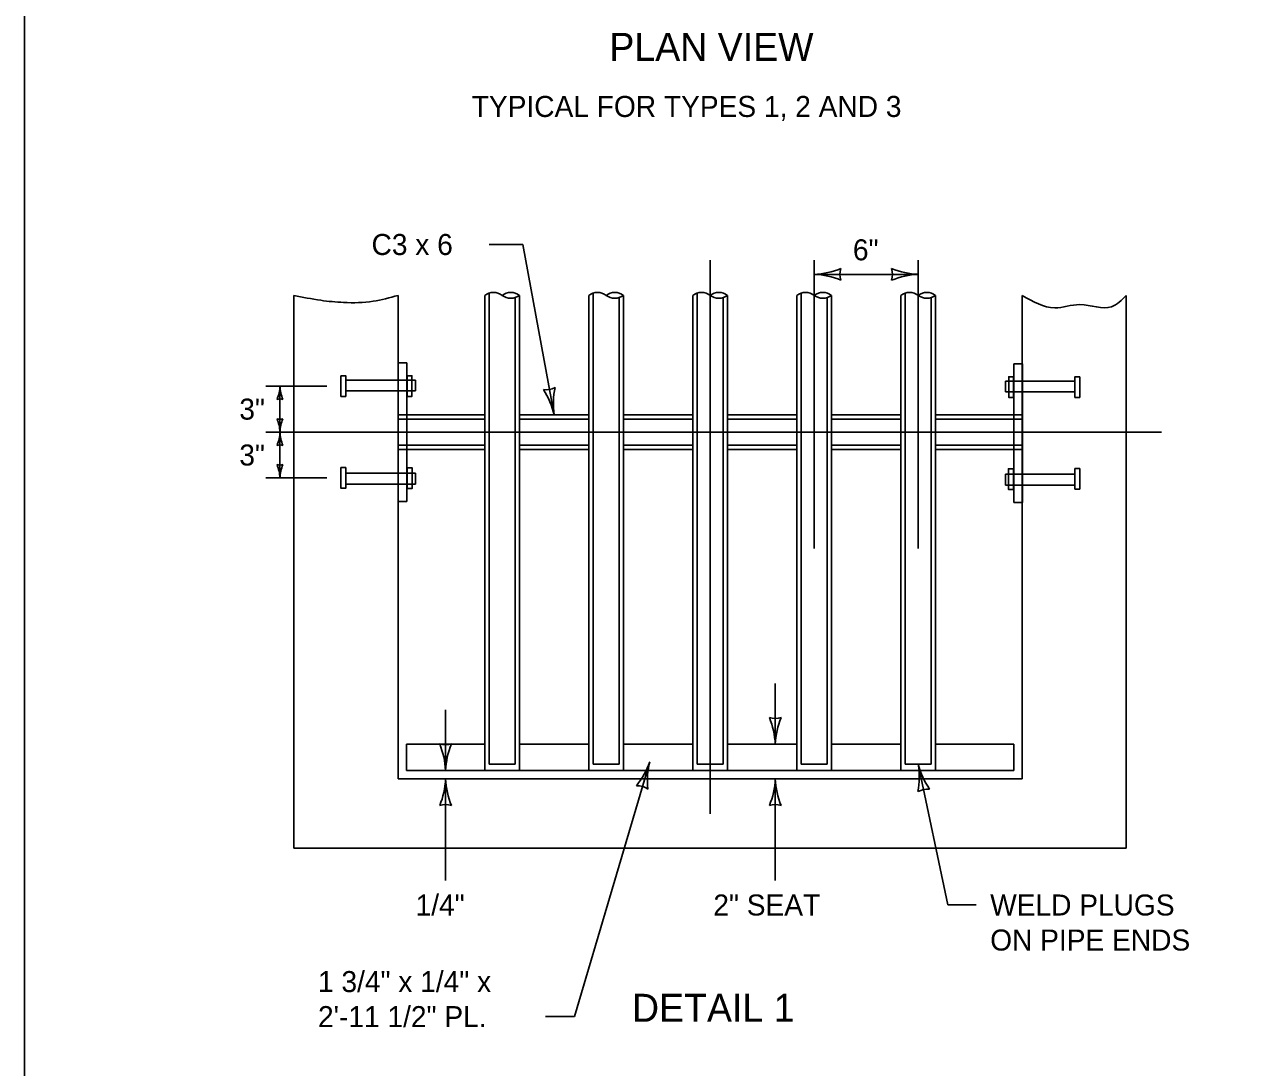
# Model space of a CAD drawing. Extents: x 49991.4 to 50021, y 49987.6 to 50011.4.
# Drawn here: x 49999.384 to 50002.895, y 49992.708 to 49995.684 of the extents above; entities that cross this region are included whole.
import ezdxf

# ---------------------------------------------------------------- set-up
doc = ezdxf.new("R2010")
doc.units = 0
for name, color, linetype in [('Level 1', 7, 'Continuous'), ('Level 2', 7, 'Continuous'), ('Level 3', 7, 'Continuous'), ('Level 4', 7, 'Continuous'), ('Level 5', 7, 'Continuous')]:
    doc.layers.add(name, color=color, linetype=linetype)

msp = doc.modelspace()

# ---------------------------------------------------------------- linework, layer by layer
at = {"layer": 'Level 1'}
for p, q in [((50000.1521, 49993.3336), (50000.1521, 49994.9114)), ((50000.449, 49993.5315), (50000.449, 49994.9114)), ((50000.6963, 49994.9114), (50000.6963, 49994.4719)), ((50000.7953, 49994.9114), (50000.7953, 49993.5553)), ((50000.9933, 49994.9114), (50000.9933, 49993.5553)), ((50001.0922, 49994.9114), (50001.0922, 49993.5553)), ((50001.2902, 49994.9114), (50001.2902, 49993.5553)), ((50001.3891, 49994.9114), (50001.3891, 49993.5553)), ((50001.587, 49994.9114), (50001.587, 49994.4656)), ((50001.686, 49994.9114), (50001.686, 49993.5553)), ((50001.8838, 49994.9114), (50001.8838, 49993.5553)), ((50001.9828, 49994.9114), (50001.9828, 49993.5553)), ((50002.2302, 49993.5315), (50002.2302, 49994.9114)), ((50002.527, 49993.3336), (50002.527, 49994.9114)), ((50000.449, 49994.5211), (50000.449, 49994.719)), ((50000.4738, 49994.719), (50000.449, 49994.719)), ((50000.4738, 49994.5211), (50000.4738, 49994.719)), ((50002.2065, 49994.5185), (50002.2065, 49994.7164)), ((50002.2312, 49994.7164), (50002.2065, 49994.7164)), ((50002.2312, 49994.5185), (50002.2312, 49994.7164)), ((50000.4888, 49994.6695), (50000.4985, 49994.6695)), ((50000.4985, 49994.6695), (50000.4985, 49994.6387)), ((50002.1818, 49994.6669), (50002.1818, 49994.6359)), ((50002.1818, 49994.6669), (50002.1915, 49994.6669)), ((50000.4888, 49994.6387), (50000.4985, 49994.6387)), ((50002.1915, 49994.6359), (50002.1818, 49994.6359)), ((50000.449, 49994.5706), (50000.6963, 49994.5706)), ((50000.7953, 49994.5706), (50000.9933, 49994.5706)), ((50001.0927, 49994.5706), (50001.2902, 49994.5706)), ((50001.3891, 49994.5706), (50001.587, 49994.5706)), ((50001.686, 49994.5706), (50001.8838, 49994.5706)), ((50001.9828, 49994.5706), (50002.2302, 49994.5706)), ((50000.449, 49994.3232), (50000.449, 49994.5211)), ((50000.4738, 49994.3232), (50000.4738, 49994.5211)), ((50002.2065, 49994.3206), (50002.2065, 49994.5185)), ((50002.2312, 49994.3206), (50002.2312, 49994.5185)), ((50000.449, 49994.4716), (50000.6963, 49994.4716)), ((50000.6963, 49994.4716), (50000.6963, 49993.5553)), ((50000.7953, 49994.4716), (50000.9933, 49994.4716)), ((50001.0922, 49994.4716), (50001.2902, 49994.4716)), ((50001.3891, 49994.4716), (50001.587, 49994.4716)), ((50001.587, 49994.4716), (50001.587, 49993.5553)), ((50001.686, 49994.4716), (50001.8838, 49994.4716)), ((50001.9828, 49994.4716), (50002.2302, 49994.4716)), ((50000.4894, 49994.4037), (50000.4985, 49994.4037)), ((50000.4985, 49994.4037), (50000.4985, 49994.3727)), ((50002.1818, 49994.4009), (50002.1818, 49994.37)), ((50002.1818, 49994.4009), (50002.1907, 49994.4009)), ((50000.4894, 49994.3727), (50000.4985, 49994.3727)), ((50002.1818, 49994.37), (50002.1907, 49994.37)), ((50000.4738, 49994.3232), (50000.449, 49994.3232)), ((50002.2312, 49994.3206), (50002.2065, 49994.3206)), ((50000.4728, 49993.6305), (50000.6963, 49993.6305)), ((50000.4728, 49993.6305), (50000.4728, 49993.5553)), ((50000.7953, 49993.6305), (50000.9933, 49993.6305)), ((50001.0922, 49993.6305), (50001.2902, 49993.6305)), ((50001.3891, 49993.6305), (50001.587, 49993.6305)), ((50001.686, 49993.6305), (50001.8838, 49993.6305)), ((50001.9828, 49993.6305), (50002.2065, 49993.6305)), ((50002.2065, 49993.6305), (50002.2065, 49993.5553)), ((50000.4728, 49993.5553), (50002.2065, 49993.5553)), ((50000.449, 49993.5315), (50002.2302, 49993.5315)), ((50000.1521, 49993.3336), (50002.527, 49993.3336))]:
    msp.add_line(p, q, dxfattribs=at)
for points in [[(49999.3835, 49998.9992), (50016.7501, 49998.9992), (50016.7501, 49987.7988), (49999.3835, 49987.7988)], [(50000.4747, 49994.6819), (50000.4747, 49994.623), (50000.4888, 49994.623), (50000.4888, 49994.6819)], [(50002.2054, 49994.6791), (50002.2054, 49994.6203), (50002.1915, 49994.6203), (50002.1915, 49994.6791)], [(50000.4754, 49994.4192), (50000.4754, 49994.3605), (50000.4894, 49994.3605), (50000.4894, 49994.4192)], [(50002.2048, 49994.4165), (50002.2048, 49994.3577), (50002.1907, 49994.3577), (50002.1907, 49994.4165)]]:
    msp.add_lwpolyline(points, close=True, dxfattribs=at)
for centre, major_axis, start_param, end_param in [((50000.7211, 49994.8789), (0, 0.0408), 5.632065, 6.934304), ((50000.7706, 49994.8789), (0, 0.0408), 5.632065, 6.934304), ((50000.7706, 49994.9439), (0, -0.0408), 5.632066, 6.934305), ((50001.018, 49994.8789), (0, 0.0408), 5.632065, 6.934304), ((50001.0675, 49994.8789), (0, 0.0408), 5.632065, 6.934304), ((50001.0675, 49994.9439), (0, -0.0408), 5.632066, 6.934305), ((50001.3149, 49994.8789), (0, 0.0408), 5.632065, 6.934304), ((50001.3643, 49994.8789), (0, 0.0408), 5.632065, 6.934304), ((50001.3643, 49994.9439), (0, -0.0408), 5.632066, 6.934305), ((50001.6117, 49994.8789), (0, 0.0408), 5.632065, 6.934304), ((50001.6612, 49994.8789), (0, 0.0408), 5.632065, 6.934304), ((50001.6612, 49994.9439), (0, -0.0408), 5.632066, 6.934305), ((50001.9086, 49994.8789), (0, 0.0408), 5.632065, 6.934304), ((50001.9581, 49994.8789), (0, 0.0408), 5.632065, 6.934304), ((50001.9581, 49994.9439), (0, -0.0408), 5.632066, 6.934305)]:
    msp.add_ellipse(centre, major_axis=major_axis, ratio=0.99996, start_param=start_param, end_param=end_param, dxfattribs=at)
for points in [[(50000.1521, 49994.9114), (50000.2283, 49994.8974), (50000.2937, 49994.8912), (50000.3779, 49994.8944), (50000.449, 49994.9114)], [(50002.2302, 49994.9114), (50002.3229, 49994.8757), (50002.3945, 49994.885), (50002.4849, 49994.8789), (50002.527, 49994.9114)]]:
    msp.add_spline(points, degree=3, dxfattribs=at)
at = {"layer": 'Level 3'}
for p, q in [((50000.7093, 49995.0566), (50000.8046, 49995.0566)), ((50000.8046, 49995.0566), (50000.8943, 49994.5706)), ((50001.6365, 49994.9714), (50001.9333, 49994.9714)), ((50000.246, 49994.6524), (50000.0721, 49994.6524)), ((50000.1121, 49994.6524), (50000.1121, 49994.5212)), ((50000.1121, 49994.5212), (50000.1121, 49994.3905)), ((50000.246, 49994.3905), (50000.0721, 49994.3905)), ((50001.5253, 49993.6305), (50001.5253, 49993.8039)), ((50000.5846, 49993.5553), (50000.5846, 49993.7287)), ((50000.9524, 49992.853), (50001.1672, 49993.5803)), ((50002.018, 49993.1716), (50001.9334, 49993.5731)), ((50000.5846, 49993.5315), (50000.5846, 49993.2416)), ((50001.5253, 49993.5315), (50001.5253, 49993.2416)), ((50002.0986, 49993.1716), (50002.018, 49993.1716)), ((50000.8702, 49992.853), (50000.9524, 49992.853))]:
    msp.add_line(p, q, dxfattribs=at)
for centre, radius, start, end in [((50001.625, 49995.2041), 0.233, 272.8273, 292.0772), ((50001.6273, 49994.7493), 0.2223, 67.456, 87.6395), ((50001.7647, 49994.9714), 0.0548, 162.1388, 197.8612), ((50001.9425, 49995.1936), 0.2223, 247.456, 267.6395), ((50001.8051, 49994.9714), 0.0548, 342.1388, 17.8612), ((50001.9448, 49994.7387), 0.233, 92.8273, 112.0772), ((50000.001, 49994.657), 0.1112, 337.456, 357.6395), ((50000.2285, 49994.6581), 0.1165, 182.8273, 202.0772), ((50000.871, 49994.6967), 0.0548, 262.5961, 298.3185), ((50001.1144, 49994.6019), 0.2223, 167.9133, 188.0968), ((50000.1121, 49994.5883), 0.0274, 72.1388, 107.8612), ((50000.6675, 49994.5171), 0.233, 13.2846, 32.5344), ((50000.1121, 49994.5853), 0.0274, 252.1388, 287.8612), ((49999.9957, 49994.5155), 0.1165, 2.8273, 22.0772), ((50000.2232, 49994.5166), 0.1112, 157.456, 177.6395), ((50000.001, 49994.5258), 0.1112, 337.456, 357.6395), ((50000.2285, 49994.5269), 0.1165, 182.8273, 202.0772), ((50000.1121, 49994.4571), 0.0274, 72.1388, 107.8612), ((50000.1121, 49994.4546), 0.0274, 252.1388, 287.8612), ((49999.9957, 49994.3848), 0.1165, 2.8273, 22.0772), ((50000.2232, 49994.3859), 0.1112, 157.456, 177.6395), ((50000.9568, 49993.652), 0.2223, 321.0021, 341.1856), ((50001.3936, 49993.5254), 0.233, 166.3734, 185.6232), ((50001.7141, 49993.5362), 0.2223, 349.3614, 9.5449), ((50002.1587, 49993.6324), 0.233, 194.7327, 213.9825), ((50001.1309, 49993.4573), 0.0548, 55.6849, 91.4073), ((50001.9598, 49993.4476), 0.0548, 84.0442, 119.7666)]:
    msp.add_arc(centre, radius, start, end, dxfattribs=at)
for centre, major_axis, start_param, end_param in [((50001.5253, 49993.7587), (0, -0.0548), 5.971449, 6.594922), ((50001.2926, 49993.619), (0, 0.233), 4.761735, 5.097708), ((50001.7474, 49993.6213), (0, 0.2223), 1.177329, 1.529598), ((50000.5846, 49993.6835), (0, -0.0548), 5.971449, 6.594922), ((50000.3519, 49993.5438), (0, 0.233), 4.761735, 5.097708), ((50000.8067, 49993.5461), (0, 0.2223), 1.177329, 1.529598), ((50000.3625, 49993.5407), (0, -0.2223), 1.177329, 1.529598), ((50000.8173, 49993.543), (0, -0.233), 4.761735, 5.097708), ((50001.3032, 49993.5407), (0, -0.2223), 1.177329, 1.529598), ((50001.758, 49993.543), (0, -0.233), 4.761735, 5.097708), ((50000.5846, 49993.4033), (0, 0.0548), 5.971449, 6.594922), ((50001.5253, 49993.4033), (0, 0.0548), 5.971449, 6.594922)]:
    msp.add_ellipse(centre, major_axis=major_axis, ratio=0.99996, start_param=start_param, end_param=end_param, dxfattribs=at)
at = {"layer": 'Level 4'}
for p, q in [((50000.7088, 49994.9179), (50000.7088, 49993.5731)), ((50000.7829, 49994.9049), (50000.7829, 49993.5731)), ((50001.0057, 49994.9179), (50001.0057, 49993.5731)), ((50001.0798, 49994.9049), (50001.0798, 49993.5731)), ((50001.3025, 49994.9179), (50001.3025, 49993.5731)), ((50001.3767, 49994.9049), (50001.3767, 49993.5731)), ((50001.5994, 49994.9179), (50001.5994, 49993.5731)), ((50001.6736, 49994.9049), (50001.6736, 49993.5731)), ((50001.8962, 49994.9179), (50001.8962, 49993.5731)), ((50001.9704, 49994.9049), (50001.9704, 49993.5731)), ((50000.4888, 49994.6695), (50000.3005, 49994.6695)), ((50002.1915, 49994.6669), (50002.3796, 49994.6669)), ((50000.4888, 49994.6387), (50000.3005, 49994.6387)), ((50002.1915, 49994.6359), (50002.3796, 49994.6359)), ((50000.449, 49994.5581), (50000.6963, 49994.5581)), ((50000.7953, 49994.5581), (50000.9933, 49994.5581)), ((50001.0927, 49994.5581), (50001.2902, 49994.5581)), ((50001.3891, 49994.5581), (50001.587, 49994.5581)), ((50001.686, 49994.5581), (50001.8838, 49994.5581)), ((50001.9828, 49994.5581), (50002.2302, 49994.5581)), ((50000.449, 49994.4841), (50000.6963, 49994.4841)), ((50000.7953, 49994.4841), (50000.9933, 49994.4841)), ((50001.0922, 49994.4841), (50001.2902, 49994.4841)), ((50001.3891, 49994.4841), (50001.587, 49994.4841)), ((50001.686, 49994.4841), (50001.8838, 49994.4841)), ((50001.9828, 49994.4841), (50002.2302, 49994.4841)), ((50000.4894, 49994.4037), (50000.3005, 49994.4037)), ((50002.1907, 49994.4009), (50002.3796, 49994.4009)), ((50000.4894, 49994.3727), (50000.3005, 49994.3727)), ((50002.1907, 49994.37), (50002.3796, 49994.37)), ((50000.7088, 49993.5731), (50000.7829, 49993.5731)), ((50001.0057, 49993.5731), (50001.0798, 49993.5731)), ((50001.3025, 49993.5731), (50001.3767, 49993.5731)), ((50001.5994, 49993.5731), (50001.6736, 49993.5731)), ((50001.8962, 49993.5731), (50001.9704, 49993.5731))]:
    msp.add_line(p, q, dxfattribs=at)
for points in [[(50000.286, 49994.6819), (50000.286, 49994.623), (50000.2999, 49994.623), (50000.2999, 49994.6819)], [(50002.3941, 49994.6791), (50002.3941, 49994.6203), (50002.3801, 49994.6203), (50002.3801, 49994.6791)], [(50000.286, 49994.4199), (50000.286, 49994.361), (50000.2999, 49994.361), (50000.2999, 49994.4199)], [(50002.3941, 49994.4172), (50002.3941, 49994.3584), (50002.3801, 49994.3584), (50002.3801, 49994.4172)]]:
    msp.add_lwpolyline(points, close=True, dxfattribs=at)
at = {"layer": 'Level 5'}
for p, q in [((50001.3396, 49995.0114), (50001.3396, 49993.4315)), ((50001.6365, 49994.1888), (50001.6365, 49995.0114)), ((50001.9333, 49994.1888), (50001.9333, 49995.0114)), ((50002.627, 49994.5212), (50000.0721, 49994.5212))]:
    msp.add_line(p, q, dxfattribs=at)

# ---------------------------------------------------------------- texts
at = {"layer": 'Level 2'}
for s, height, p in [('PLAN VIEW', 0.08, (50001.0519, 49995.5806)), ('TYPICAL FOR TYPES 1, 2 AND 3', 0.06, (50000.6593, 49995.4206)), ('C3 x 6', 0.06, (50000.3734, 49995.0266)), ('6"', 0.06, (50001.7469, 49995.0114)), ('3"', 0.06, (49999.9961, 49994.5568)), ('3"', 0.06, (49999.9961, 49994.4258)), (' 1/4"', 0.06, (50000.4768, 49993.1416)), ('2" SEAT', 0.06, (50001.3486, 49993.1416)), ('WELD PLUGS ', 0.06, (50002.1386, 49993.1416)), ('ON PIPE ENDS', 0.06, (50002.1386, 49993.0416)), ('1 3/4" x 1/4" x', 0.06, (50000.2206, 49992.923)), ('DETAIL 1', 0.08, (50001.1165, 49992.8382)), ('2\'-11 1/2" PL.', 0.06, (50000.2206, 49992.823))]:
    msp.add_text(s, height=height, dxfattribs=at).set_placement(p)

doc.saveas('drawing.dxf')
